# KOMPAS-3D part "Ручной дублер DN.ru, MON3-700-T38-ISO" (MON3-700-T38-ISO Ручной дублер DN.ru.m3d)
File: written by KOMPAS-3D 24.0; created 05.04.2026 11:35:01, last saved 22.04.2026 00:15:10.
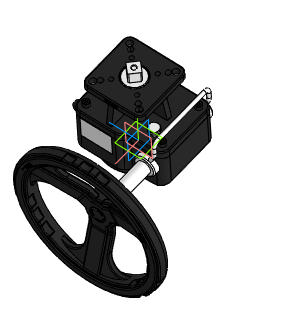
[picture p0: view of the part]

Document properties: Автор: R2D2; Полное имя файла: E:\Работа\Зайцев\Аксессуары для пневмоприводов\Ручной дублер DN.ru\MON3-700-T38-ISO Ручной дублер DN.ru\MON3-700-T38-ISO Ручной дублер DN.ru.m3d

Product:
- Part/product: Ручной дублер DN.ru  | designation MON3-700-T38-ISO
    Масса: 6.9
    Раздел спецификации: Прочие изделия
    Примечание: D290-00338

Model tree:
1. Операция без истории:2

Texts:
  MON3-700-T38-ISO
